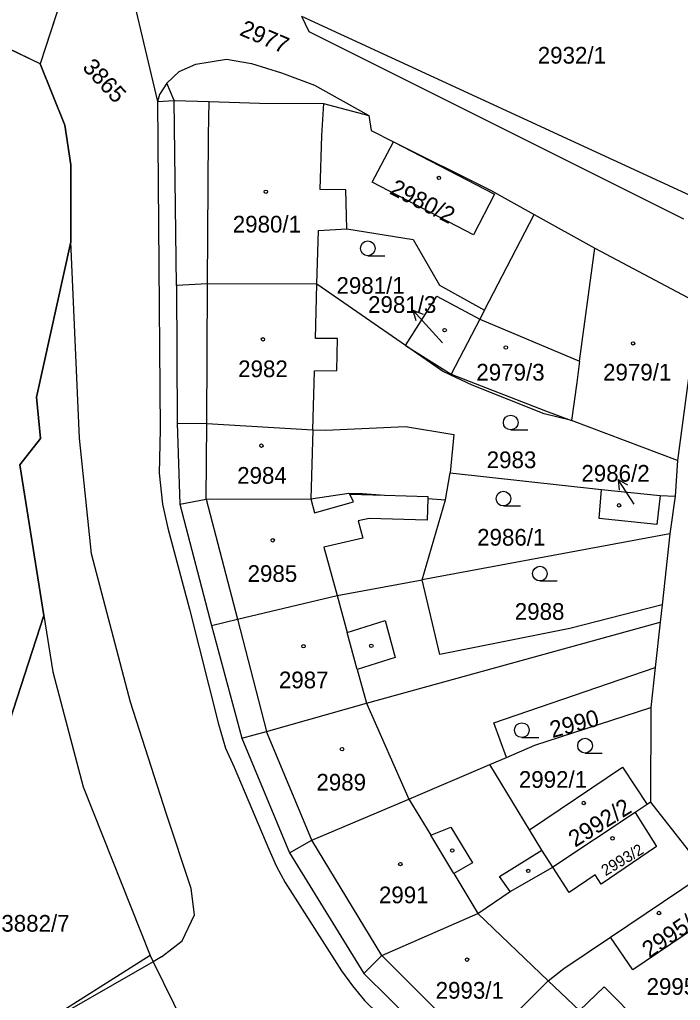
# Model space of a CAD drawing. Extents: x -527335 to -526256, y -1079142 to -1077836.
# Drawn here: x -526750.1 to -526682.7, y -1078714.2 to -1078614.4 of the extents above; entities that cross this region are included whole.
import ezdxf

# ---------------------------------------------------------------- set-up
doc = ezdxf.new("R2010")
doc.units = 0
for name, color, linetype in [('Hranice parcel', 7, 'Continuous'), ('Parcelní čísla', 7, 'Continuous'), ('Pop  PČ popisy', 7, 'Continuous'), ('Vnitřní kresba', 7, 'Continuous'), ('Vrstva 54', 7, 'Continuous'), ('Značky budov', 7, 'Continuous'), ('Značky kultur', 7, 'Continuous')]:
    doc.layers.add(name, color=color, linetype=linetype)

msp = doc.modelspace()

# ---------------------------------------------------------------- linework, layer by layer
at = {"layer": 'Hranice parcel'}
for p, q in [((-526739.77, -1078606.94), (-526736.02, -1078622.71)), ((-526744.33, -1078607.7), (-526747.97, -1078618.86)), ((-526747.97, -1078618.86), (-526766.12, -1078610.17)), ((-526721.35, -1078614.01), (-526679.1, -1078633.49)), ((-526736.02, -1078622.71), (-526734.32, -1078622.61)), ((-526734.09, -1078641.43), (-526734.32, -1078622.61)), ((-526702.72, -1078643.94), (-526697.66, -1078634.2)), ((-526734.09, -1078641.43), (-526734.02, -1078655.45)), ((-526710.74, -1078647.55), (-526719.77, -1078641.31)), ((-526702.72, -1078643.94), (-526703.19, -1078644.85)), ((-526680.92, -1078643.22), (-526683.06, -1078659.24)), ((-526734.02, -1078655.45), (-526733.74, -1078663.69)), ((-526683.06, -1078659.24), (-526693.83, -1078655.18)), ((-526683.06, -1078659.24), (-526683.29, -1078662.87)), ((-526706.68, -1078663.24), (-526706.21, -1078660.51)), ((-526706.21, -1078660.51), (-526690.77, -1078662.18)), ((-526690.77, -1078662.18), (-526684.82, -1078662.79)), ((-526684.82, -1078662.79), (-526683.29, -1078662.87)), ((-526683.29, -1078662.87), (-526683.84, -1078666.72)), ((-526733.74, -1078663.69), (-526730.51, -1078676.04)), ((-526709.06, -1078671.38), (-526706.68, -1078663.24)), ((-526683.84, -1078666.72), (-526709.06, -1078671.38)), ((-526683.84, -1078666.72), (-526684.62, -1078673.95)), ((-526684.62, -1078673.95), (-526684.81, -1078675.69)), ((-526684.81, -1078675.69), (-526685.32, -1078680.32)), ((-526730.51, -1078676.04), (-526727.41, -1078687.49)), ((-526685.32, -1078680.32), (-526685.77, -1078684.4)), ((-526685.77, -1078684.4), (-526685.78, -1078694.02)), ((-526727.41, -1078687.49), (-526722.57, -1078699.16)), ((-526702.15, -1078690.19), (-526700.45, -1078689.46)), ((-526698.12, -1078696.82), (-526702.15, -1078690.19)), ((-526686.15, -1078694.26), (-526687.35, -1078695.06)), ((-526685.78, -1078694.02), (-526686.15, -1078694.26)), ((-526685.78, -1078694.02), (-526680.15, -1078701.23)), ((-526687.35, -1078695.06), (-526695.75, -1078700.62)), ((-526722.57, -1078699.16), (-526714.99, -1078711.45)), ((-526689.86, -1078707.76), (-526680.84, -1078701.69)), ((-526736.78, -1078709.62), (-526766.02, -1078728.13)), ((-526705.09, -1078721.19), (-526714.99, -1078711.45))]:
    msp.add_line(p, q, dxfattribs=at)
for points in [[(-526747.6, -1078675.03), (-526750.05, -1078659.68), (-526747.95, -1078657.02), (-526748.33, -1078652.79), (-526744.86, -1078637), (-526744.86, -1078629.16), (-526745.47, -1078625.12), (-526747.97, -1078618.86)], [(-526736.02, -1078622.71), (-526735.76, -1078656.09), (-526735.85, -1078660.53), (-526735.52, -1078663.69), (-526734.95, -1078666.12), (-526732.77, -1078674.37), (-526729.8, -1078686.09), (-526729.09, -1078688.53), (-526728.19, -1078690.47), (-526724.67, -1078698.8), (-526723.91, -1078700.57), (-526723.02, -1078702.2), (-526717.26, -1078711.17), (-526716.15, -1078712.7), (-526714.92, -1078714.22), (-526690.33, -1078738.18), (-526681.83, -1078746.32), (-526638.92, -1078788.12), (-526632.34, -1078794.49), (-526593.57, -1078832.2), (-526592.15, -1078831.2)], [(-526734.32, -1078622.61), (-526730.77, -1078622.72), (-526725.62, -1078622.89), (-526719.1, -1078622.92), (-526714.49, -1078624.12), (-526714.26, -1078625.67), (-526711.99, -1078626.8), (-526702.11, -1078631.73), (-526697.66, -1078634.2)], [(-526714.14, -1078630.93), (-526711.99, -1078626.8), (-526701.67, -1078632.15), (-526703.83, -1078636.29), (-526714.14, -1078630.93)], [(-526697.66, -1078634.2), (-526691.45, -1078637.64), (-526680.92, -1078643.22)], [(-526719.77, -1078641.31), (-526719.61, -1078635.84), (-526716.73, -1078635.68), (-526709.97, -1078636.74), (-526707.28, -1078641.39), (-526702.72, -1078643.94)], [(-526719.77, -1078641.31), (-526730.91, -1078641.27), (-526734.09, -1078641.43)], [(-526720.2, -1078656.11), (-526720.03, -1078650.11), (-526717.74, -1078650.09), (-526717.68, -1078646.84), (-526719.93, -1078646.81), (-526719.77, -1078641.31)], [(-526710.74, -1078647.55), (-526707.55, -1078642.52), (-526703.19, -1078644.85)], [(-526703.19, -1078644.85), (-526706.1, -1078650.46), (-526706.15, -1078650.55)], [(-526703.19, -1078644.85), (-526693.01, -1078649.14), (-526693.31, -1078651.32), (-526693.83, -1078655.18)], [(-526706.15, -1078650.55), (-526707, -1078650.14), (-526710.74, -1078647.55)], [(-526693.83, -1078655.18), (-526696.62, -1078654.48), (-526703.97, -1078651.59), (-526706.15, -1078650.55)], [(-526734.02, -1078655.45), (-526731, -1078655.49), (-526720.2, -1078656.11)], [(-526720.2, -1078656.11), (-526718.9, -1078656.16), (-526710.76, -1078655.78), (-526705.84, -1078656.59), (-526706.21, -1078660.51)], [(-526733.74, -1078663.69), (-526731.05, -1078663.17), (-526720.41, -1078663.15), (-526716.54, -1078662.56), (-526715.12, -1078662.61), (-526712.88, -1078662.78), (-526708.47, -1078662.91), (-526708.48, -1078663.11), (-526706.68, -1078663.24)], [(-526684.82, -1078662.79), (-526685.16, -1078665.77), (-526691.04, -1078665.14), (-526690.77, -1078662.18)], [(-526730.51, -1078676.04), (-526727.88, -1078675.39), (-526717.73, -1078672.98), (-526709.06, -1078671.38)], [(-526684.62, -1078673.95), (-526694.02, -1078676.34), (-526707.27, -1078678.98), (-526709.06, -1078671.38)], [(-526766.02, -1078728.13), (-526758.54, -1078708.63), (-526747.6, -1078675.03)], [(-526747.6, -1078675.03), (-526746.69, -1078680.74), (-526743.6, -1078692.45), (-526736.78, -1078709.62)], [(-526727.41, -1078687.49), (-526724.92, -1078686.81), (-526714.74, -1078683.95), (-526684.81, -1078675.69)], [(-526700.45, -1078689.46), (-526701.77, -1078685.93), (-526685.32, -1078680.32)], [(-526700.45, -1078689.46), (-526697.56, -1078688.23), (-526685.77, -1078684.4)], [(-526722.57, -1078699.16), (-526720.3, -1078697.87), (-526710.4, -1078693.71), (-526702.15, -1078690.19)], [(-526698.12, -1078696.82), (-526688.65, -1078690.47), (-526686.15, -1078694.26)], [(-526687.35, -1078695.06), (-526685.17, -1078698.54), (-526690.81, -1078702.35), (-526691.43, -1078701.42), (-526694.08, -1078703.21), (-526695.75, -1078700.62)], [(-526695.75, -1078700.62), (-526696.86, -1078698.9), (-526698.12, -1078696.82)], [(-526714.99, -1078711.45), (-526713.16, -1078709.62), (-526703.39, -1078705.34), (-526700.09, -1078703.11), (-526695.75, -1078700.62)], [(-526680.84, -1078701.69), (-526678.6, -1078705.01), (-526687.59, -1078711.07), (-526689.86, -1078707.76)], [(-526696.22, -1078712.19), (-526694.61, -1078710.96), (-526689.86, -1078707.76)], [(-526736.78, -1078709.62), (-526736.47, -1078710.26), (-526732.32, -1078718.67), (-526731.58, -1078720.17)], [(-526696.22, -1078712.19), (-526703.4, -1078719.37), (-526705.09, -1078721.19)], [(-526685.11, -1078719.62), (-526687.43, -1078717.35), (-526686.72, -1078716.65), (-526690.52, -1078712.81), (-526693.04, -1078715.23), (-526696.22, -1078712.19)]]:
    msp.add_lwpolyline(points, dxfattribs=at)
at = {"layer": 'Pop  PČ popisy'}
for p, q in [((-526707.99, -1078646.16), (-526709.998, -1078643.93)), ((-526709.998, -1078643.93), (-526708.956, -1078644.339)), ((-526709.998, -1078643.93), (-526709.7, -1078645.009)), ((-526706.99, -1078647.28), (-526707.99, -1078646.16)), ((-526687.46, -1078663.68), (-526689.094, -1078661.163)), ((-526689.094, -1078661.163), (-526688.129, -1078661.73)), ((-526689.094, -1078661.163), (-526688.969, -1078662.276))]:
    msp.add_line(p, q, dxfattribs=at)
at = {"layer": 'Vnitřní kresba'}
for p, q in [((-526721.35, -1078614.01), (-526720.61, -1078615.59)), ((-526720.61, -1078615.59), (-526682.42, -1078634.66)), ((-526733.8, -1078619.65), (-526732.12, -1078618.91)), ((-526732.12, -1078618.91), (-526729, -1078618.39)), ((-526729, -1078618.39), (-526726.45, -1078618.83)), ((-526726.45, -1078618.83), (-526723.38, -1078619.8)), ((-526735.05, -1078620.83), (-526733.8, -1078619.65)), ((-526723.38, -1078619.8), (-526720.03, -1078621.04)), ((-526735.05, -1078620.83), (-526735.82, -1078621.98)), ((-526734.32, -1078622.61), (-526735.05, -1078620.83)), ((-526735.82, -1078621.98), (-526736.02, -1078622.71)), ((-526720.03, -1078621.04), (-526714.49, -1078624.12)), ((-526730.82, -1078626.16), (-526730.77, -1078622.72)), ((-526719.1, -1078622.92), (-526719.32, -1078626.18)), ((-526730.91, -1078641.27), (-526730.82, -1078626.16)), ((-526719.32, -1078626.18), (-526719.48, -1078631.65)), ((-526716.82, -1078631.7), (-526719.48, -1078631.65)), ((-526716.73, -1078635.68), (-526716.82, -1078631.7)), ((-526743.96, -1078656.98), (-526744.86, -1078637)), ((-526693.01, -1078649.14), (-526691.45, -1078637.64)), ((-526731, -1078655.49), (-526730.91, -1078641.27)), ((-526710.74, -1078647.55), (-526706.1, -1078650.46)), ((-526706.1, -1078650.46), (-526696.49, -1078654.18)), ((-526696.49, -1078654.18), (-526693.83, -1078655.18)), ((-526731.05, -1078663.17), (-526731, -1078655.49)), ((-526720.2, -1078656.11), (-526720.41, -1078663.15)), ((-526742.73, -1078668.75), (-526743.96, -1078656.98)), ((-526716.06, -1078663.45), (-526716.43, -1078662.67)), ((-526716.43, -1078662.67), (-526712.88, -1078662.78)), ((-526731.05, -1078663.17), (-526727.88, -1078675.39)), ((-526720.41, -1078663.15), (-526720.03, -1078664.56)), ((-526720.03, -1078664.56), (-526716.06, -1078663.45)), ((-526708.48, -1078663.11), (-526708.54, -1078665.33)), ((-526714.45, -1078665.16), (-526715.56, -1078665.4)), ((-526715.56, -1078665.4), (-526715.11, -1078667.16)), ((-526708.54, -1078665.33), (-526714.45, -1078665.16)), ((-526715.11, -1078667.16), (-526719.07, -1078668.07)), ((-526738.77, -1078683.83), (-526742.73, -1078668.75)), ((-526719.07, -1078668.07), (-526717.73, -1078672.98)), ((-526717.73, -1078672.98), (-526716.7, -1078676.75)), ((-526727.88, -1078675.39), (-526724.92, -1078686.81)), ((-526716.7, -1078676.75), (-526712.84, -1078675.54)), ((-526712.84, -1078675.54), (-526711.82, -1078679.28)), ((-526715.67, -1078680.52), (-526716.7, -1078676.75)), ((-526711.82, -1078679.28), (-526715.67, -1078680.52)), ((-526715.67, -1078680.52), (-526714.74, -1078683.95)), ((-526735.12, -1078695.13), (-526738.77, -1078683.83)), ((-526714.74, -1078683.95), (-526710.4, -1078693.71)), ((-526720.3, -1078697.87), (-526724.92, -1078686.81)), ((-526710.4, -1078693.71), (-526708.18, -1078697.39)), ((-526732.58, -1078702.79), (-526735.12, -1078695.13)), ((-526708.18, -1078697.39), (-526706.12, -1078696.55)), ((-526706.12, -1078696.55), (-526703.94, -1078700.21)), ((-526705.84, -1078701.28), (-526708.18, -1078697.39)), ((-526713.16, -1078709.62), (-526720.3, -1078697.87)), ((-526701.17, -1078701.58), (-526696.86, -1078698.9)), ((-526703.94, -1078700.21), (-526705.84, -1078701.28)), ((-526705.84, -1078701.28), (-526703.39, -1078705.34)), ((-526700.09, -1078703.11), (-526701.17, -1078701.58)), ((-526732.26, -1078705.49), (-526732.58, -1078702.79)), ((-526733.5, -1078708.13), (-526732.26, -1078705.49)), ((-526696.22, -1078712.19), (-526703.39, -1078705.34)), ((-526735.6, -1078709.76), (-526733.5, -1078708.13)), ((-526735.6, -1078709.76), (-526736.47, -1078710.26)), ((-526713.16, -1078709.62), (-526703.4, -1078719.37)), ((-526736.47, -1078710.26), (-526738.29, -1078711.31)), ((-526738.29, -1078711.31), (-526747.88, -1078716.79))]:
    msp.add_line(p, q, dxfattribs=at)
at = {"layer": 'Vrstva 54'}
for points in [[(-526703.39, -1078543.02), (-526715.41, -1078561.03), (-526728.83, -1078581.13), (-526744.33, -1078607.7), (-526747.97, -1078618.86), (-526766.12, -1078610.17), (-526763.31, -1078600.18), (-526763.05, -1078599.24), (-526753.29, -1078556.18), (-526750.73, -1078522.13), (-526753.35, -1078482.54), (-526753.77, -1078479.82), (-526755.3, -1078470.16), (-526758.4, -1078472.62), (-526766.27, -1078446.58), (-526780.95, -1078423.56)], [(-526747.97, -1078618.86), (-526745.47, -1078625.12), (-526744.86, -1078629.16), (-526744.86, -1078637), (-526748.33, -1078652.79), (-526747.95, -1078657.02), (-526750.05, -1078659.68), (-526747.6, -1078675.03), (-526758.54, -1078708.63)]]:
    msp.add_lwpolyline(points, dxfattribs=at)
at = {"layer": 'Značky budov'}
for centre in [(-526707.347, -1078630.479), (-526724.977, -1078631.889), (-526706.767, -1078645.979), (-526725.277, -1078646.909), (-526700.527, -1078647.739), (-526687.567, -1078647.329), (-526725.427, -1078657.739), (-526688.997, -1078663.809), (-526724.277, -1078667.369), (-526721.147, -1078678.149), (-526714.237, -1078678.109), (-526717.217, -1078688.629), (-526692.597, -1078694.109), (-526689.667, -1078697.699), (-526705.987, -1078698.939), (-526711.277, -1078700.319), (-526698.247, -1078701.019), (-526684.926, -1078705.303), (-526704.477, -1078710.049)]:
    msp.add_circle(centre, 0.175, dxfattribs=at)
at = {"layer": 'Značky kultur'}
for p, q in [((-526714.593, -1078638.4), (-526712.843, -1078638.4)), ((-526700.033, -1078656.13), (-526698.283, -1078656.13)), ((-526700.773, -1078663.87), (-526699.023, -1078663.87)), ((-526697.063, -1078671.5), (-526695.313, -1078671.5)), ((-526698.903, -1078687.44), (-526697.153, -1078687.44)), ((-526692.463, -1078689.02), (-526690.713, -1078689.02))]:
    msp.add_line(p, q, dxfattribs=at)
for centre in [(-526714.593, -1078637.65), (-526700.033, -1078655.38), (-526700.773, -1078663.12), (-526697.063, -1078670.75), (-526698.903, -1078686.69), (-526692.463, -1078688.27)]:
    msp.add_circle(centre, 0.75, dxfattribs=at)

# ---------------------------------------------------------------- texts
at = {"layer": 'Parcelní čísla'}
for s, height, rotation, p in [('2977', 1.7, 337, (-526727.751, -1078615.913)), ('3865', 1.7, 313, (-526743.751, -1078619.304)), ('2980/2', 1.7, 333, (-526712.475, -1078632.047)), ('2990', 1.7, 15, (-526695.79, -1078687.501)), ('2992/2', 1.7, 32, (-526693.472, -1078698.662)), ('2993/2', 1.14, 31, (-526690.376, -1078701.568)), ('2995/2', 1.7, 34, (-526685.915, -1078709.943))]:
    msp.add_text(s, height=height, rotation=rotation, dxfattribs=at).set_placement(p)
for s, p in [('2932/1', (-526697.28, -1078618.85)), ('2980/1', (-526728.35, -1078636.04)), ('2981/1', (-526717.785, -1078642.28)), ('2981/3', (-526714.565, -1078644.22)), ('2982', (-526727.8, -1078650.76)), ('2979/3', (-526703.535, -1078651.11)), ('2979/1', (-526690.625, -1078651.11)), ('2983', (-526702.48, -1078660.02)), ('2984', (-526727.9, -1078661.61)), ('2986/2', (-526692.835, -1078661.4)), ('2986/1', (-526703.455, -1078667.91)), ('2985', (-526726.839, -1078671.6)), ('2988', (-526699.62, -1078675.46)), ('2987', (-526723.65, -1078682.43)), ('2992/1', (-526699.205, -1078692.56)), ('2989', (-526719.829, -1078692.84)), ('2991', (-526713.459, -1078704.31)), ('3882/7', (-526751.925, -1078707.2)), ('2993/1', (-526707.68, -1078714.02)), ('2995/1', (-526686.195, -1078713.63))]:
    msp.add_text(s, height=1.7, dxfattribs=at).set_placement(p)

doc.saveas('drawing.dxf')
